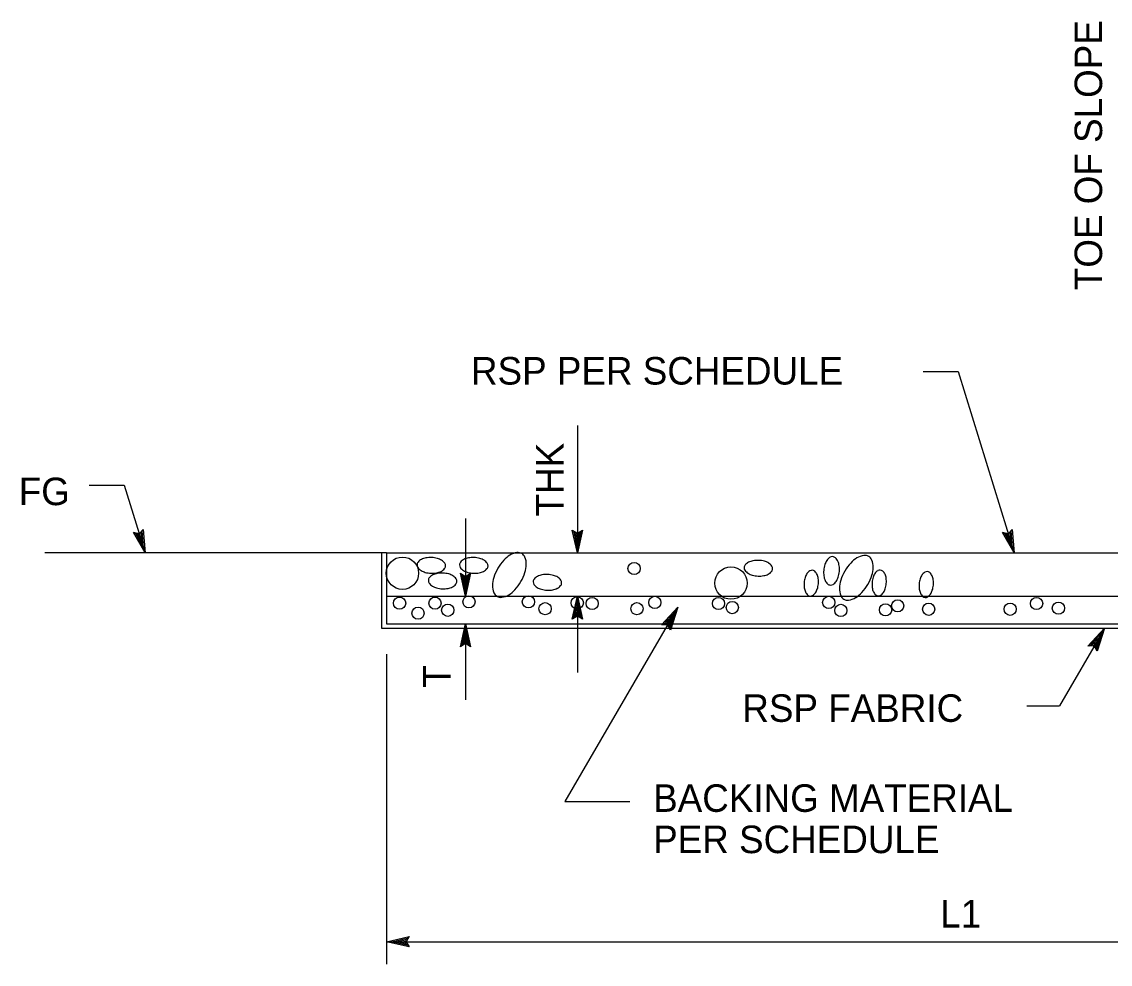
# Model space of a CAD drawing. Extents: x 6707692 to 6708868, y 1870875 to 1871658.
# Drawn here: x 6708383.5 to 6708616.9, y 1871262.9 to 1871464.9 of the extents above; entities that cross this region are included whole.
import ezdxf

# ---------------------------------------------------------------- set-up
doc = ezdxf.new("R2010")
doc.units = 0
doc.layers.add('Level 60', color=7, linetype='Continuous')

msp = doc.modelspace()

# ---------------------------------------------------------------- linework, layer by layer
at = {"layer": 'Level 60'}
for p, q in [((6708502.63, 1871378.31), (6708502.63, 1871351.02)), ((6708478.63, 1871358.38), (6708478.63, 1871341.75)), ((6708407.48, 1871355.4), (6708407.48, 1871355.4)), ((6708409.57, 1871356.04), (6708409.57, 1871356.04)), ((6708502.63, 1871351.02), (6708501.54, 1871355.94)), ((6708501.54, 1871355.94), (6708501.54, 1871355.94)), ((6708501.54, 1871355.94), (6708502.63, 1871355.28)), ((6708502.63, 1871352.16), (6708501.84, 1871355.74)), ((6708502.63, 1871353.28), (6708502.12, 1871355.6)), ((6708502.63, 1871354.42), (6708502.41, 1871355.41)), ((6708502.63, 1871355.28), (6708503.73, 1871355.94)), ((6708503.73, 1871355.94), (6708502.63, 1871351.02)), ((6708503.44, 1871355.76), (6708502.63, 1871352.15)), ((6708503.14, 1871355.57), (6708502.63, 1871353.28)), ((6708502.86, 1871355.42), (6708502.63, 1871354.42)), ((6708503.73, 1871355.94), (6708503.73, 1871355.94)), ((6708593.78, 1871355.4), (6708593.78, 1871355.4)), ((6708595.87, 1871356.04), (6708595.87, 1871356.04)), ((6708502.63, 1871351.02), (6708502.63, 1871352.82)), ((6708409.97, 1871351.02), (6708409.97, 1871351.02)), ((6708460.69, 1871334.86), (6708460.69, 1871351.02)), ((6708461.68, 1871351.02), (6708712.86, 1871351.02)), ((6708461.68, 1871351.02), (6708461.68, 1871335.85)), ((6708502.63, 1871351.02), (6708502.63, 1871351.02)), ((6708596.27, 1871351.02), (6708596.27, 1871351.02)), ((6708478.63, 1871341.75), (6708477.54, 1871346.66)), ((6708477.54, 1871346.66), (6708477.54, 1871346.66)), ((6708477.54, 1871346.66), (6708478.63, 1871346.01)), ((6708478.63, 1871342.89), (6708477.84, 1871346.47)), ((6708478.63, 1871344.01), (6708478.12, 1871346.33)), ((6708478.64, 1871345.14), (6708478.42, 1871346.13)), ((6708478.63, 1871346.01), (6708479.73, 1871346.66)), ((6708479.73, 1871346.66), (6708478.63, 1871341.75)), ((6708479.44, 1871346.49), (6708478.63, 1871342.88)), ((6708479.14, 1871346.3), (6708478.63, 1871344.01)), ((6708478.86, 1871346.15), (6708478.64, 1871345.14)), ((6708479.73, 1871346.66), (6708479.73, 1871346.66)), ((6708478.63, 1871341.75), (6708478.63, 1871343.55)), ((6708461.68, 1871341.75), (6708712.86, 1871341.75)), ((6708478.63, 1871341.75), (6708478.63, 1871341.75)), ((6708501.53, 1871336.83), (6708502.63, 1871341.75)), ((6708501.83, 1871337.01), (6708502.63, 1871340.62)), ((6708502.63, 1871341.75), (6708502.63, 1871325.43)), ((6708502.63, 1871341.75), (6708502.63, 1871339.95)), ((6708502.63, 1871341.75), (6708502.63, 1871341.75)), ((6708502.63, 1871341.75), (6708503.72, 1871336.83)), ((6708502.63, 1871340.61), (6708503.43, 1871337.02)), ((6708524.18, 1871339.4), (6708499.94, 1871297.74)), ((6708502.63, 1871337.49), (6708501.53, 1871336.83)), ((6708502.12, 1871337.2), (6708502.63, 1871339.48)), ((6708502.4, 1871337.34), (6708502.63, 1871338.35)), ((6708502.63, 1871339.48), (6708503.14, 1871337.17)), ((6708502.63, 1871338.35), (6708502.85, 1871337.36)), ((6708503.72, 1871336.83), (6708502.63, 1871337.49)), ((6708520.66, 1871335.6), (6708524.18, 1871339.4)), ((6708521.01, 1871335.6), (6708523.6, 1871338.39)), ((6708523.6, 1871338.38), (6708522.44, 1871334.79)), ((6708524.18, 1871339.4), (6708522.61, 1871334.46)), ((6708461.68, 1871335.85), (6708712.86, 1871335.85)), ((6708477.55, 1871330.93), (6708478.65, 1871335.85)), ((6708478.65, 1871335.85), (6708478.65, 1871334.05)), ((6708478.65, 1871335.85), (6708478.65, 1871335.85)), ((6708478.65, 1871335.85), (6708479.74, 1871330.93)), ((6708478.65, 1871335.85), (6708478.65, 1871319.53)), ((6708501.53, 1871336.83), (6708501.53, 1871336.83)), ((6708503.72, 1871336.83), (6708503.72, 1871336.83)), ((6708521.98, 1871335.61), (6708520.66, 1871335.6)), ((6708521.37, 1871335.62), (6708523.01, 1871337.39)), ((6708521.7, 1871335.6), (6708522.42, 1871336.38)), ((6708522.61, 1871334.46), (6708521.98, 1871335.61)), ((6708522.42, 1871336.38), (6708522.1, 1871335.39)), ((6708523.01, 1871337.39), (6708522.27, 1871335.06)), ((6708713.84, 1871334.86), (6708460.69, 1871334.86)), ((6708477.84, 1871331.11), (6708478.65, 1871334.72)), ((6708478.14, 1871331.3), (6708478.65, 1871333.58)), ((6708478.65, 1871334.71), (6708479.44, 1871331.12)), ((6708478.65, 1871333.58), (6708479.16, 1871331.27)), ((6708615.66, 1871334.86), (6708606, 1871318.28)), ((6708612.1, 1871331.07), (6708615.62, 1871334.87)), ((6708612.45, 1871331.08), (6708615.03, 1871333.87)), ((6708612.81, 1871331.1), (6708614.45, 1871332.86)), ((6708614.45, 1871332.86), (6708613.7, 1871330.54)), ((6708615.03, 1871333.86), (6708613.88, 1871330.26)), ((6708615.62, 1871334.87), (6708614.04, 1871329.94)), ((6708478.65, 1871331.59), (6708477.55, 1871330.93)), ((6708477.55, 1871330.93), (6708477.55, 1871330.93)), ((6708478.42, 1871331.44), (6708478.65, 1871332.45)), ((6708478.65, 1871332.45), (6708478.87, 1871331.46)), ((6708479.74, 1871330.93), (6708478.65, 1871331.59)), ((6708479.74, 1871330.93), (6708479.74, 1871330.93)), ((6708613.41, 1871331.09), (6708612.1, 1871331.07)), ((6708613.14, 1871331.08), (6708613.86, 1871331.86)), ((6708614.04, 1871329.94), (6708613.41, 1871331.09)), ((6708613.86, 1871331.86), (6708613.54, 1871330.86)), ((6708461.68, 1871329.33), (6708461.68, 1871262.87)), ((6708599.01, 1871318.28), (6708606, 1871318.28)), ((6708499.94, 1871297.74), (6708513.89, 1871297.74)), ((6708461.68, 1871267.7), (6708466.59, 1871268.79)), ((6708461.68, 1871267.7), (6708712.86, 1871267.7)), ((6708461.68, 1871267.7), (6708463.47, 1871267.7)), ((6708466.59, 1871266.6), (6708461.68, 1871267.7)), ((6708461.68, 1871267.7), (6708461.68, 1871267.7)), ((6708466.42, 1871266.89), (6708462.81, 1871267.7)), ((6708462.82, 1871267.7), (6708466.4, 1871268.5)), ((6708463.94, 1871267.7), (6708466.26, 1871268.21)), ((6708466.22, 1871267.19), (6708463.94, 1871267.7)), ((6708465.07, 1871267.7), (6708466.06, 1871267.92)), ((6708466.08, 1871267.47), (6708465.07, 1871267.7)), ((6708466.59, 1871268.79), (6708465.94, 1871267.7)), ((6708465.94, 1871267.7), (6708466.59, 1871266.6)), ((6708466.59, 1871268.79), (6708466.59, 1871268.79)), ((6708466.59, 1871266.6), (6708466.59, 1871266.6))]:
    msp.add_line(p, q, dxfattribs=at)
for points in [[(6708576.76, 1871389.9), (6708584.27, 1871389.9), (6708596.27, 1871351.02)], [(6708397.97, 1871365.55), (6708405.48, 1871365.55), (6708409.97, 1871351.02)], [(6708461.68, 1871351.02), (6708388.46, 1871351.02)]]:
    msp.add_lwpolyline(points, dxfattribs=at)
for points in [[(6708409.57, 1871356.04), (6708409.97, 1871351.02), (6708407.47, 1871355.4), (6708407.8, 1871355.31), (6708409.63, 1871352.11), (6708409.34, 1871355.79), (6708409.11, 1871355.54), (6708409.3, 1871353.18), (6708408.13, 1871355.23), (6708408.46, 1871355.15), (6708408.97, 1871354.27), (6708408.89, 1871355.29), (6708408.71, 1871355.09), (6708407.47, 1871355.4), (6708408.71, 1871355.09)], [(6708595.87, 1871356.04), (6708596.27, 1871351.02), (6708593.78, 1871355.4), (6708594.11, 1871355.31), (6708595.94, 1871352.11), (6708595.65, 1871355.79), (6708595.42, 1871355.54), (6708595.61, 1871353.18), (6708594.44, 1871355.23), (6708594.77, 1871355.15), (6708595.28, 1871354.27), (6708595.19, 1871355.29), (6708595.02, 1871355.09), (6708593.78, 1871355.4), (6708595.02, 1871355.09)]]:
    msp.add_lwpolyline(points, close=True, dxfattribs=at)
for centre, radius in [((6708465.13, 1871346.68), 3.47), ((6708514.79, 1871347.69), 1.31), ((6708535.56, 1871344.56), 3.47), ((6708464.52, 1871340.25), 1.31), ((6708472.11, 1871340.25), 1.31), ((6708474.84, 1871338.74), 1.31), ((6708479.39, 1871340.55), 1.31), ((6708492.14, 1871340.55), 1.31), ((6708495.71, 1871339.08), 1.31), ((6708502.61, 1871340.31), 1.31), ((6708505.81, 1871340.18), 1.31), ((6708515.41, 1871339.08), 1.31), ((6708519.23, 1871340.43), 1.31), ((6708532.89, 1871340.18), 1.31), ((6708535.85, 1871339.32), 1.31), ((6708556.53, 1871340.43), 1.31), ((6708559.11, 1871338.71), 1.31), ((6708568.71, 1871338.83), 1.31), ((6708571.3, 1871339.69), 1.31), ((6708577.95, 1871338.95), 1.31), ((6708595.43, 1871338.95), 1.31), ((6708601.09, 1871340.18), 1.31), ((6708605.77, 1871339.2), 1.31), ((6708468.47, 1871338.13), 1.31)]:
    msp.add_circle(centre, radius, dxfattribs=at)
for centre, radius, start, end in [((6708470.19, 1871347.67), 2.21, 116.4195, 140.6402), ((6708470.8, 1871346.45), 3.57, 100.3875, 116.4195), ((6708471.15, 1871344.54), 5.51, 87.4953, 100.3875), ((6708471.15, 1871344.54), 5.51, 74.6031, 87.4953), ((6708471.66, 1871346.41), 3.57, 58.5711, 74.6031), ((6708472.37, 1871347.57), 2.21, 34.3504, 58.5711), ((6708479.3, 1871347.67), 2.21, 116.4195, 140.6402), ((6708479.9, 1871346.45), 3.57, 100.3875, 116.4195), ((6708480.25, 1871344.54), 5.51, 87.4953, 100.3875), ((6708480.25, 1871344.54), 5.51, 74.6031, 87.4953), ((6708480.77, 1871346.41), 3.57, 58.5711, 74.6031), ((6708481.48, 1871347.57), 2.21, 34.3504, 58.5711), ((6708494.09, 1871342.82), 9.82, 137.3954, 149.9552), ((6708491.49, 1871345.21), 6.29, 121.6811, 137.3954), ((6708490.19, 1871347.31), 3.82, 97.5555, 121.6811), ((6708489.9, 1871349.5), 1.61, 59.9552, 97.5555), ((6708489.9, 1871349.5), 1.61, 22.3549, 59.9552), ((6708487.86, 1871348.66), 3.82, 358.2293, 22.3549), ((6708540.92, 1871345.84), 3.57, 100.3875, 116.4195), ((6708541.27, 1871343.93), 5.51, 87.4953, 100.3875), ((6708541.27, 1871343.93), 5.51, 74.6031, 87.4953), ((6708541.79, 1871345.81), 3.57, 58.5711, 74.6031), ((6708559.08, 1871347.45), 3.57, 146.1522, 162.1843), ((6708557.95, 1871348.21), 2.21, 121.9316, 146.1522), ((6708557.3, 1871349.26), 0.975, 85.0765, 121.9316), ((6708557.3, 1871349.26), 0.975, 48.2213, 85.0765), ((6708556.47, 1871348.33), 2.21, 24.0007, 48.2213), ((6708555.23, 1871347.78), 3.57, 7.9686, 24.0007), ((6708565.86, 1871344.61), 6.29, 121.6811, 137.3954), ((6708564.57, 1871346.7), 3.82, 97.5555, 121.6811), ((6708564.28, 1871348.9), 1.61, 59.9552, 97.5555), ((6708564.28, 1871348.9), 1.61, 22.3549, 59.9552), ((6708562.23, 1871348.06), 3.82, 358.2293, 22.3549), ((6708469.23, 1871348.45), 0.975, 140.6402, 177.4953), ((6708469.23, 1871348.45), 0.975, 177.4953, 214.3504), ((6708470.26, 1871349.15), 2.21, 214.3504, 238.5711), ((6708470.97, 1871350.31), 3.57, 238.5711, 254.6031), ((6708471.48, 1871352.18), 5.51, 254.6031, 267.4953), ((6708471.83, 1871350.28), 3.57, 280.3875, 296.4195), ((6708472.44, 1871349.06), 2.21, 296.4195, 320.6402), ((6708473.39, 1871348.27), 0.975, 320.6402, 357.4953), ((6708473.39, 1871348.27), 0.975, 357.4953, 34.3504), ((6708478.34, 1871348.45), 0.975, 140.6402, 177.4953), ((6708478.34, 1871348.45), 0.975, 177.4953, 214.3504), ((6708479.36, 1871349.15), 2.21, 214.3504, 238.5711), ((6708480.07, 1871350.31), 3.57, 238.5711, 254.6031), ((6708480.59, 1871352.18), 5.51, 254.6031, 267.4953), ((6708480.94, 1871350.28), 3.57, 280.3875, 296.4195), ((6708481.54, 1871349.06), 2.21, 296.4195, 320.6402), ((6708482.5, 1871348.27), 0.975, 320.6402, 357.4953), ((6708482.5, 1871348.27), 0.975, 357.4953, 34.3504), ((6708494.09, 1871342.82), 9.82, 149.9552, 162.515), ((6708482.02, 1871349.8), 9.82, 329.9552, 342.515), ((6708485.39, 1871348.74), 6.29, 342.515, 358.2293), ((6708539.36, 1871347.85), 0.975, 140.6402, 177.4953), ((6708539.36, 1871347.85), 0.975, 177.4953, 214.3504), ((6708540.38, 1871348.55), 2.21, 214.3504, 238.5711), ((6708540.31, 1871347.06), 2.21, 116.4195, 140.6402), ((6708542.56, 1871348.45), 2.21, 296.4195, 320.6402), ((6708542.49, 1871346.97), 2.21, 34.3504, 58.5711), ((6708543.52, 1871347.67), 0.975, 320.6402, 357.4953), ((6708543.52, 1871347.67), 0.975, 357.4953, 34.3504), ((6708553.53, 1871345.47), 2.01, 121.9316, 146.1522), ((6708552.93, 1871346.43), 0.886, 85.0765, 121.9316), ((6708552.93, 1871346.43), 0.886, 48.2213, 85.0765), ((6708552.18, 1871345.59), 2.01, 24.0007, 48.2213), ((6708560.93, 1871346.85), 5.51, 175.0765, 187.9686), ((6708560.93, 1871346.85), 5.51, 162.1843, 175.0765), ((6708553.31, 1871347.51), 5.51, 342.1843, 355.0765), ((6708553.31, 1871347.51), 5.51, 355.0765, 7.9686), ((6708568.46, 1871342.21), 9.82, 149.9552, 162.515), ((6708568.46, 1871342.21), 9.82, 137.3954, 149.9552), ((6708559.76, 1871348.13), 6.29, 342.515, 358.2293), ((6708568.1, 1871345.52), 2.01, 121.9316, 146.1522), ((6708567.51, 1871346.48), 0.886, 85.0765, 121.9316), ((6708567.51, 1871346.48), 0.886, 48.2213, 85.0765), ((6708566.76, 1871345.64), 2.01, 24.0007, 48.2213), ((6708578.19, 1871345.19), 2.01, 121.9316, 146.1522), ((6708577.59, 1871346.14), 0.886, 85.0765, 121.9316), ((6708577.59, 1871346.14), 0.886, 48.2213, 85.0765), ((6708576.84, 1871345.31), 2.01, 24.0007, 48.2213), ((6708471.66, 1871345.12), 0.975, 140.6402, 177.4953), ((6708471.66, 1871345.12), 0.975, 177.4953, 214.3504), ((6708472.69, 1871345.82), 2.21, 214.3504, 238.5711), ((6708472.62, 1871344.34), 2.21, 116.4195, 140.6402), ((6708471.48, 1871352.18), 5.51, 267.4953, 280.3875), ((6708473.23, 1871343.12), 3.57, 100.3875, 116.4195), ((6708473.58, 1871341.21), 5.51, 87.4953, 100.3875), ((6708473.58, 1871341.21), 5.51, 74.6031, 87.4953), ((6708474.09, 1871343.08), 3.57, 58.5711, 74.6031), ((6708474.8, 1871344.24), 2.21, 34.3504, 58.5711), ((6708475.82, 1871344.94), 0.975, 320.6402, 357.4953), ((6708475.82, 1871344.94), 0.975, 357.4953, 34.3504), ((6708480.59, 1871352.18), 5.51, 267.4953, 280.3875), ((6708490.72, 1871343.88), 6.29, 162.515, 178.2293), ((6708482.02, 1871349.8), 9.82, 317.3954, 329.9552), ((6708494.13, 1871344.82), 0.975, 140.6402, 177.4953), ((6708494.13, 1871344.82), 0.975, 177.4953, 214.3504), ((6708495.08, 1871344.03), 2.21, 116.4195, 140.6402), ((6708495.69, 1871342.81), 3.57, 100.3875, 116.4195), ((6708496.04, 1871340.91), 5.51, 87.4953, 100.3875), ((6708496.04, 1871340.91), 5.51, 74.6031, 87.4953), ((6708496.55, 1871342.78), 3.57, 58.5711, 74.6031), ((6708497.26, 1871343.94), 2.21, 34.3504, 58.5711), ((6708498.29, 1871344.64), 0.975, 320.6402, 357.4953), ((6708498.29, 1871344.64), 0.975, 357.4953, 34.3504), ((6708541.09, 1871349.71), 3.57, 238.5711, 254.6031), ((6708541.6, 1871351.58), 5.51, 254.6031, 267.4953), ((6708541.6, 1871351.58), 5.51, 267.4953, 280.3875), ((6708541.95, 1871349.67), 3.57, 280.3875, 296.4195), ((6708556.23, 1871344.24), 5.01, 175.0765, 187.9686), ((6708556.23, 1871344.24), 5.01, 162.1843, 175.0765), ((6708554.56, 1871344.78), 3.25, 146.1522, 162.1843), ((6708551.05, 1871345.09), 3.25, 7.9686, 24.0007), ((6708549.31, 1871344.84), 5.01, 355.0765, 7.9686), ((6708559.01, 1871346.59), 3.57, 187.9686, 204.0007), ((6708557.76, 1871346.03), 2.21, 204.0007, 228.2213), ((6708556.28, 1871346.16), 2.21, 301.9316, 326.1522), ((6708555.15, 1871346.92), 3.57, 326.1522, 342.1843), ((6708565.09, 1871343.28), 6.29, 162.515, 178.2293), ((6708556.4, 1871349.19), 9.82, 329.9552, 342.515), ((6708570.81, 1871344.3), 5.01, 175.0765, 187.9686), ((6708570.81, 1871344.3), 5.01, 162.1843, 175.0765), ((6708569.13, 1871344.84), 3.25, 146.1522, 162.1843), ((6708565.63, 1871345.14), 3.25, 7.9686, 24.0007), ((6708563.88, 1871344.89), 5.01, 342.1843, 355.0765), ((6708563.88, 1871344.89), 5.01, 355.0765, 7.9686), ((6708580.89, 1871343.96), 5.01, 162.1843, 175.0765), ((6708579.21, 1871344.5), 3.25, 146.1522, 162.1843), ((6708575.71, 1871344.8), 3.25, 7.9686, 24.0007), ((6708573.96, 1871344.56), 5.01, 355.0765, 7.9686), ((6708473.39, 1871346.98), 3.57, 238.5711, 254.6031), ((6708473.91, 1871348.85), 5.51, 254.6031, 267.4953), ((6708473.91, 1871348.85), 5.51, 267.4953, 280.3875), ((6708474.26, 1871346.94), 3.57, 280.3875, 296.4195), ((6708474.86, 1871345.72), 2.21, 296.4195, 320.6402), ((6708488.26, 1871343.96), 3.82, 178.2293, 202.3549), ((6708486.21, 1871343.12), 1.61, 202.3549, 239.9552), ((6708484.62, 1871347.41), 6.29, 301.6811, 317.3954), ((6708495.15, 1871345.52), 2.21, 214.3504, 238.5711), ((6708495.86, 1871346.68), 3.57, 238.5711, 254.6031), ((6708496.37, 1871348.55), 5.51, 254.6031, 267.4953), ((6708496.37, 1871348.55), 5.51, 267.4953, 280.3875), ((6708496.72, 1871346.64), 3.57, 280.3875, 296.4195), ((6708497.33, 1871345.42), 2.21, 296.4195, 320.6402), ((6708554.49, 1871344), 3.25, 187.9686, 204.0007), ((6708553.36, 1871343.5), 2.01, 204.0007, 228.2213), ((6708552.01, 1871343.61), 2.01, 301.9316, 326.1522), ((6708550.98, 1871344.3), 3.25, 326.1522, 342.1843), ((6708549.31, 1871344.84), 5.01, 342.1843, 355.0765), ((6708556.94, 1871345.11), 0.975, 228.2213, 265.0765), ((6708556.94, 1871345.11), 0.975, 265.0765, 301.9316), ((6708562.63, 1871343.35), 3.82, 178.2293, 202.3549), ((6708559, 1871346.8), 6.29, 301.6811, 317.3954), ((6708556.4, 1871349.19), 9.82, 317.3954, 329.9552), ((6708569.06, 1871344.05), 3.25, 187.9686, 204.0007), ((6708567.93, 1871343.55), 2.01, 204.0007, 228.2213), ((6708566.59, 1871343.66), 2.01, 301.9316, 326.1522), ((6708565.56, 1871344.35), 3.25, 326.1522, 342.1843), ((6708580.89, 1871343.96), 5.01, 175.0765, 187.9686), ((6708579.15, 1871343.72), 3.25, 187.9686, 204.0007), ((6708578.02, 1871343.21), 2.01, 204.0007, 228.2213), ((6708576.67, 1871343.33), 2.01, 301.9316, 326.1522), ((6708575.64, 1871344.02), 3.25, 326.1522, 342.1843), ((6708573.96, 1871344.56), 5.01, 342.1843, 355.0765), ((6708486.21, 1871343.12), 1.61, 239.9552, 277.5555), ((6708485.92, 1871345.31), 3.82, 277.5555, 301.6811), ((6708552.61, 1871342.66), 0.886, 228.2213, 265.0765), ((6708552.61, 1871342.66), 0.886, 265.0765, 301.9316), ((6708560.58, 1871342.51), 1.61, 202.3549, 239.9552), ((6708560.58, 1871342.51), 1.61, 239.9552, 277.5555), ((6708560.29, 1871344.7), 3.82, 277.5555, 301.6811), ((6708567.18, 1871342.71), 0.886, 228.2213, 265.0765), ((6708567.18, 1871342.71), 0.886, 265.0765, 301.9316), ((6708577.27, 1871342.37), 0.886, 228.2213, 265.0765), ((6708577.27, 1871342.37), 0.886, 265.0765, 301.9316)]:
    msp.add_arc(centre, radius, start, end, dxfattribs=at)

# ---------------------------------------------------------------- texts
for s, p in [('TOE OF SLOPE', (6708615.14, 1871407.35)), ('THK', (6708499.68, 1871358.85)), ('T', (6708475.45, 1871322.15))]:
    msp.add_text(s, height=5.9, rotation=90, dxfattribs=at).set_placement(p)
for s, p in [('RSP PER SCHEDULE', (6708479.82, 1871387.12)), ('FG', (6708382.86, 1871361.27)), ('RSP FABRIC', (6708538, 1871314.82)), ('BACKING MATERIAL', (6708518.88, 1871295.53)), ('PER SCHEDULE', (6708518.88, 1871286.68)), ('L1', (6708580.43, 1871270.74))]:
    msp.add_text(s, height=5.9, dxfattribs=at).set_placement(p)

doc.saveas('drawing.dxf')
